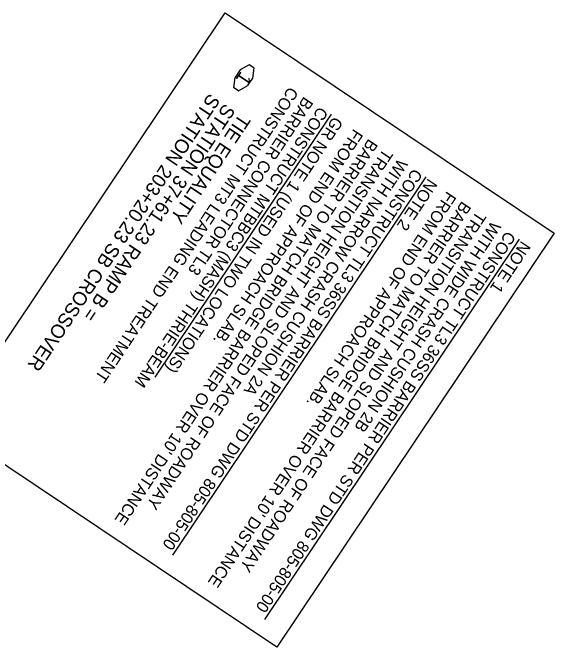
# Model space of a CAD drawing. Extents: x 1966090 to 1975830, y 788086 to 801233.
# Drawn here: x 1972095.4 to 1972368.1, y 796515.6 to 796835.1 of the extents above; entities that cross this region are included whole.
import ezdxf

# ---------------------------------------------------------------- set-up
doc = ezdxf.new("R2010")
doc.units = 0
doc.layers.add('RD_HY_XS_Slope', color=7, linetype='Continuous')
doc.layers.add('RD_Sketch6', color=7, linetype='Continuous')

msp = doc.modelspace()

# ---------------------------------------------------------------- linework, layer by layer
at = {"layer": 'RD_HY_XS_Slope'}
for p, q in [((1972214.5, 796808.83), (1972210, 796806.27)), ((1972216.77, 796807.31), (1972214.5, 796808.83)), ((1972210, 796806.27), (1972207.42, 796802.42)), ((1972216.77, 796807.31), (1972216.12, 796802.17)), ((1972206.77, 796797.28), (1972207.42, 796802.42)), ((1972216.12, 796802.17), (1972213.54, 796798.32)), ((1972209.04, 796795.76), (1972213.54, 796798.32)), ((1972209.04, 796795.76), (1972206.77, 796797.28))]:
    msp.add_line(p, q, dxfattribs=at)
at = {"layer": 'RD_Sketch6'}
for p, q in [((1972167.13, 796651.56), (1972255.86, 796784.05)), ((1972175.95, 796561.98), (1972303.56, 796752.53)), ((1972222.32, 796529.51), (1972350.58, 796721.04))]:
    msp.add_line(p, q, dxfattribs=at)
msp.add_lwpolyline([(1972368.11, 796724.18), (1972228.41, 796515.56), (1972062.74, 796626.5), (1972202.44, 796835.12)], close=True, dxfattribs=at)

# ---------------------------------------------------------------- texts
at = {"layer": 'RD_HY_XS_Slope'}
for s, p in [('1', (1972210.38, 796805.99)), ('STATION 203+20.23 SB CROSSOVER', (1972194.42, 796794.91)), ('STATION 37+61.23 RAMP B =', (1972202.05, 796789.81)), ('TIE EQUALITY', (1972209.67, 796784.7))]:
    msp.add_text(s, height=7, rotation=236.2115, dxfattribs=at).set_placement(p)
at = {"layer": 'RD_Sketch6'}
for s, height, rotation, p in [('CONSTRUCT MT3 LEADING END TREATMENT', 5.9996, 236.2179, (1972234.64, 796798.24)), ('BARRIER CONNECTOR TL3', 5.9996, 236.2179, (1972242.12, 796793.23)), ('CONSTRUCT MTBBC3 (MASH) THRIE-BEAM', 5.9996, 236.2179, (1972249.6, 796788.23)), ('GR NOTE 1 (USED IN TWO LOCATIONS)', 5.9996, 236.2179, (1972257.08, 796783.22)), ('FROM END OF APPROACH SLAB.', 5.9996, 236.3077, (1972267.18, 796777.01)), ("BARRIER TO MATCH BRIDGE BARRIER OVER 10' DISTANCE", 5.9996, 236.3077, (1972274.67, 796772.02)), ('TRANSITION HEIGHT AND SLOPED FACE OF ROADWAY', 5.9996, 236.3077, (1972282.16, 796767.03)), ('WITH NARROW CRASH CUSHION 2A', 5.9996, 236.3077, (1972289.65, 796762.04)), ('CONSTRUCT TL3 36SS BARRIER PER STD DWG 805-805-00', 5.9996, 236.3077, (1972297.13, 796757.05)), ('NOTE 2', 6, 236.3077, (1972304.62, 796752.05)), ('FROM END OF APPROACH SLAB.', 5.9996, 236.3077, (1972314.14, 796745.57)), ("BARRIER TO MATCH BRIDGE BARRIER OVER 10' DISTANCE", 5.9996, 236.3077, (1972321.63, 796740.58)), ('TRANSITION HEIGHT AND SLOPED FACE OF ROADWAY', 5.9996, 236.3077, (1972329.12, 796735.58)), ('WITH WIDE CRASH CUSHION 2B', 5.9996, 236.3077, (1972336.6, 796730.59)), ('CONSTRUCT TL3 36SS BARRIER PER STD DWG 805-805-00', 5.9996, 236.3077, (1972344.09, 796725.6)), ('NOTE 1', 6, 236.3077, (1972351.58, 796720.61))]:
    msp.add_text(s, height=height, rotation=rotation, dxfattribs=at).set_placement(p)

doc.saveas('drawing.dxf')
